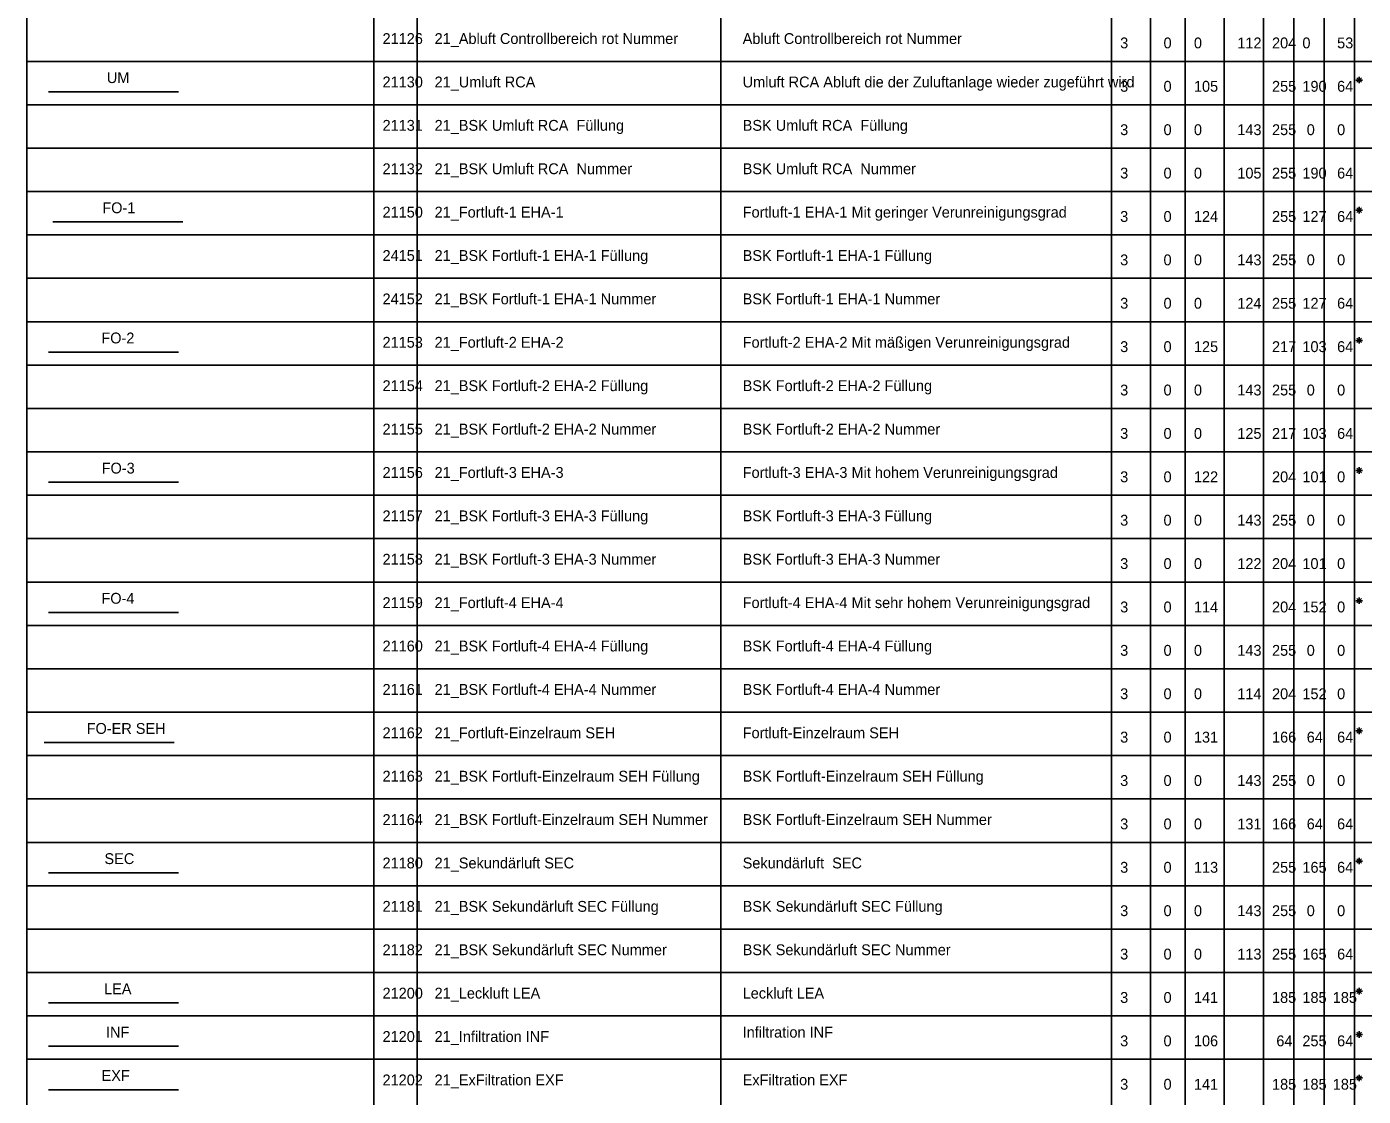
# Model space of a CAD drawing. Extents: x -26 to 55, y -9 to 161.
# Drawn here: x 0 to 30.8, y 52.15 to 76.8 of the extents above; entities that cross this region are included whole.
import ezdxf

# ---------------------------------------------------------------- set-up
doc = ezdxf.new("R2010")
doc.units = 0
for name, color, linetype in [('21_ExFiltration EXF', 7, 'Continuous'), ('21_Fortluft-1 EHA-1', 7, 'Continuous'), ('21_Fortluft-2 EHA-2', 7, 'Continuous'), ('21_Fortluft-3 EHA-3', 7, 'Continuous'), ('21_Fortluft-4 EHA-4', 7, 'Continuous'), ('21_Fortluft-Einezelraum SEH', 7, 'Continuous'), ('21_Infiltration INF', 7, 'Continuous'), ('21_Leckluft LEA', 7, 'Continuous'), ('21_Sekundärluft SEC', 7, 'Continuous'), ('21_Umluft RCA', 7, 'Continuous'), ('Default', 7, 'Continuous')]:
    doc.layers.add(name, color=color, linetype=linetype)

msp = doc.modelspace()

# ---------------------------------------------------------------- linework, layer by layer
at = {"layer": '21_ExFiltration EXF'}
msp.add_line((0.5, 52.3), (3.5, 52.3), dxfattribs=at)
at = {"layer": '21_Fortluft-1 EHA-1'}
msp.add_line((0.6, 72.3), (3.6, 72.3), dxfattribs=at)
at = {"layer": '21_Fortluft-2 EHA-2'}
msp.add_line((0.5, 69.3), (3.5, 69.3), dxfattribs=at)
at = {"layer": '21_Fortluft-3 EHA-3'}
msp.add_line((0.5, 66.3), (3.5, 66.3), dxfattribs=at)
at = {"layer": '21_Fortluft-4 EHA-4'}
msp.add_line((0.5, 63.3), (3.5, 63.3), dxfattribs=at)
at = {"layer": '21_Fortluft-Einezelraum SEH'}
msp.add_line((0.4, 60.3), (3.4, 60.3), dxfattribs=at)
at = {"layer": '21_Infiltration INF'}
msp.add_line((0.5, 53.3), (3.5, 53.3), dxfattribs=at)
at = {"layer": '21_Leckluft LEA'}
msp.add_line((0.5, 54.3), (3.5, 54.3), dxfattribs=at)
at = {"layer": '21_Sekundärluft SEC'}
msp.add_line((0.5, 57.3), (3.5, 57.3), dxfattribs=at)
at = {"layer": '21_Umluft RCA'}
msp.add_line((0.5, 75.3), (3.5, 75.3), dxfattribs=at)
at = {"layer": 'Default'}
for p, q in [((0, 147), (0, 0)), ((8, 147), (8, 0)), ((9, 147), (9, 0)), ((16, 147), (16, 0)), ((25, 147), (25, 0)), ((25.9, 146.3), (25.9, 28)), ((26.7, 146.3), (26.7, 28)), ((27.6, 146.3), (27.6, 28)), ((28.5, 146.3), (28.5, 28)), ((30.6, 146.3), (30.6, 28)), ((29.2, 145.5), (29.2, 28)), ((29.9, 145.5), (29.9, 28)), ((0, 76), (30.383, 76)), ((0, 76), (33.6, 76)), ((30.634, 75.57), (30.786, 75.57)), ((30.657, 75.623), (30.763, 75.517)), ((30.763, 75.623), (30.657, 75.517)), ((30.71, 75.646), (30.71, 75.494)), ((0, 75), (33.6, 75)), ((0, 74), (33.6, 74)), ((0, 73), (33.6, 73)), ((30.634, 72.57), (30.786, 72.57)), ((30.657, 72.623), (30.763, 72.517)), ((30.763, 72.623), (30.657, 72.517)), ((30.71, 72.646), (30.71, 72.494)), ((0, 72), (33.6, 72)), ((0, 71), (33.6, 71)), ((0, 70), (33.6, 70)), ((30.657, 69.623), (30.763, 69.517)), ((30.763, 69.623), (30.657, 69.517)), ((30.71, 69.646), (30.71, 69.494)), ((30.634, 69.57), (30.786, 69.57)), ((0, 69), (33.6, 69)), ((0, 68), (33.6, 68)), ((0, 67), (33.6, 67)), ((30.634, 66.57), (30.786, 66.57)), ((30.657, 66.623), (30.763, 66.517)), ((30.763, 66.623), (30.657, 66.517)), ((30.71, 66.646), (30.71, 66.494)), ((0, 66), (33.6, 66)), ((0, 65), (33.6, 65)), ((0, 64), (33.6, 64)), ((30.634, 63.57), (30.786, 63.57)), ((30.657, 63.623), (30.763, 63.517)), ((30.763, 63.623), (30.657, 63.517)), ((30.71, 63.646), (30.71, 63.494)), ((0, 63), (33.6, 63)), ((0, 62), (33.6, 62)), ((0, 61), (33.6, 61)), ((30.634, 60.57), (30.786, 60.57)), ((30.657, 60.623), (30.763, 60.517)), ((30.763, 60.623), (30.657, 60.517)), ((30.71, 60.646), (30.71, 60.494)), ((0, 60), (33.6, 60)), ((0, 59), (33.6, 59)), ((0, 58), (33.6, 58)), ((30.657, 57.623), (30.763, 57.517)), ((30.763, 57.623), (30.657, 57.517)), ((30.71, 57.646), (30.71, 57.494)), ((30.634, 57.57), (30.786, 57.57)), ((0, 57), (33.6, 57)), ((0, 56), (33.6, 56)), ((0, 55), (33.6, 55)), ((30.634, 54.57), (30.786, 54.57)), ((30.657, 54.623), (30.763, 54.517)), ((30.763, 54.623), (30.657, 54.517)), ((30.71, 54.646), (30.71, 54.494)), ((0, 54), (33.6, 54)), ((30.657, 53.623), (30.763, 53.517)), ((30.763, 53.623), (30.657, 53.517)), ((30.71, 53.646), (30.71, 53.494)), ((30.634, 53.57), (30.786, 53.57)), ((0, 53), (33.6, 53)), ((30.634, 52.57), (30.786, 52.57)), ((30.657, 52.623), (30.763, 52.517)), ((30.763, 52.623), (30.657, 52.517)), ((30.71, 52.646), (30.71, 52.494))]:
    msp.add_line(p, q, dxfattribs=at)

# ---------------------------------------------------------------- texts
at = {"layer": '21_ExFiltration EXF'}
msp.add_text('EXF ', height=0.25, dxfattribs=at).set_placement((1.725, 52.5))
at = {"layer": '21_Fortluft-1 EHA-1'}
msp.add_text('FO-1', height=0.25, dxfattribs=at).set_placement((1.742, 72.5))
at = {"layer": '21_Fortluft-2 EHA-2'}
msp.add_text('FO-2', height=0.25, dxfattribs=at).set_placement((1.72, 69.5))
at = {"layer": '21_Fortluft-3 EHA-3'}
msp.add_text('FO-3', height=0.25, dxfattribs=at).set_placement((1.727, 66.5))
at = {"layer": '21_Fortluft-4 EHA-4'}
msp.add_text('FO-4', height=0.25, dxfattribs=at).set_placement((1.722, 63.5))
at = {"layer": '21_Fortluft-Einezelraum SEH'}
msp.add_text('FO-ER SEH', height=0.25, dxfattribs=at).set_placement((1.381, 60.5))
at = {"layer": '21_Infiltration INF'}
msp.add_text('INF', height=0.25, dxfattribs=at).set_placement((1.827, 53.5))
at = {"layer": '21_Leckluft LEA'}
msp.add_text('LEA', height=0.25, dxfattribs=at).set_placement((1.782, 54.5))
at = {"layer": '21_Sekundärluft SEC'}
msp.add_text('SEC', height=0.25, dxfattribs=at).set_placement((1.792, 57.5))
at = {"layer": '21_Umluft RCA'}
msp.add_text('UM', height=0.25, dxfattribs=at).set_placement((1.846, 75.5))
at = {"layer": 'Default'}
for s, p in [('21126', (8.2, 76.4)), ('21_Abluft Controllbereich rot Nummer', (9.4, 76.4)), ('Abluft Controllbereich rot Nummer', (16.5, 76.4)), ('3', (25.2, 76.3)), ('0', (26.2, 76.3)), ('0', (26.9, 76.3)), ('112', (27.9, 76.3)), ('204', (28.7, 76.3)), ('0', (29.4, 76.3)), ('53', (30.2, 76.3)), ('21130', (8.2, 75.4)), ('21_Umluft RCA ', (9.4, 75.4)), ('Umluft RCA Abluft die der Zuluftanlage wieder zugeführt wird', (16.5, 75.4)), ('3', (25.2, 75.3)), ('0', (26.2, 75.3)), ('105', (26.9, 75.3)), ('255', (28.7, 75.3)), ('190', (29.4, 75.3)), ('64', (30.2, 75.3)), ('21131', (8.2, 74.4)), ('21_BSK Umluft RCA  Füllung', (9.4, 74.4)), ('BSK Umluft RCA  Füllung', (16.5, 74.4)), ('3', (25.2, 74.3)), ('0', (26.2, 74.3)), ('0', (26.9, 74.3)), ('143', (27.9, 74.3)), ('255', (28.7, 74.3)), ('0', (29.5, 74.3)), ('0', (30.2, 74.3)), ('21132', (8.2, 73.4)), ('21_BSK Umluft RCA  Nummer', (9.4, 73.4)), ('BSK Umluft RCA  Nummer', (16.5, 73.4)), ('3', (25.2, 73.3)), ('0', (26.2, 73.3)), ('0', (26.9, 73.3)), ('105', (27.9, 73.3)), ('255', (28.7, 73.3)), ('190', (29.4, 73.3)), ('64', (30.2, 73.3)), ('21150', (8.2, 72.4)), ('21_Fortluft-1 EHA-1', (9.4, 72.4)), ('Fortluft-1 EHA-1 Mit geringer Verunreinigungsgrad', (16.5, 72.4)), ('3', (25.2, 72.3)), ('0', (26.2, 72.3)), ('124', (26.9, 72.3)), ('255', (28.7, 72.3)), ('127', (29.4, 72.3)), ('64', (30.2, 72.3)), ('24151', (8.2, 71.4)), ('21_BSK Fortluft-1 EHA-1 Füllung', (9.4, 71.4)), ('BSK Fortluft-1 EHA-1 Füllung', (16.5, 71.4)), ('3', (25.2, 71.3)), ('0', (26.2, 71.3)), ('0', (26.9, 71.3)), ('143', (27.9, 71.3)), ('255', (28.7, 71.3)), ('0', (29.5, 71.3)), ('0', (30.2, 71.3)), ('24152', (8.2, 70.4)), ('21_BSK Fortluft-1 EHA-1 Nummer', (9.4, 70.4)), ('BSK Fortluft-1 EHA-1 Nummer', (16.5, 70.4)), ('3', (25.2, 70.3)), ('0', (26.2, 70.3)), ('0', (26.9, 70.3)), ('124', (27.9, 70.3)), ('255', (28.7, 70.3)), ('127', (29.4, 70.3)), ('64', (30.2, 70.3)), ('21153', (8.2, 69.4)), ('21_Fortluft-2 EHA-2', (9.4, 69.4)), ('Fortluft-2 EHA-2 Mit mäßigen Verunreinigungsgrad', (16.5, 69.4)), ('3', (25.2, 69.3)), ('0', (26.2, 69.3)), ('125', (26.9, 69.3)), ('217', (28.7, 69.3)), ('103', (29.4, 69.3)), ('64', (30.2, 69.3)), ('21154', (8.2, 68.4)), ('21_BSK Fortluft-2 EHA-2 Füllung', (9.4, 68.4)), ('BSK Fortluft-2 EHA-2 Füllung', (16.5, 68.4)), ('3', (25.2, 68.3)), ('0', (26.2, 68.3)), ('0', (26.9, 68.3)), ('143', (27.9, 68.3)), ('255', (28.7, 68.3)), ('0', (29.5, 68.3)), ('0', (30.2, 68.3)), ('21155', (8.2, 67.4)), ('21_BSK Fortluft-2 EHA-2 Nummer', (9.4, 67.4)), ('BSK Fortluft-2 EHA-2 Nummer', (16.5, 67.4)), ('3', (25.2, 67.3)), ('0', (26.2, 67.3)), ('0', (26.9, 67.3)), ('125', (27.9, 67.3)), ('217', (28.7, 67.3)), ('103', (29.4, 67.3)), ('64', (30.2, 67.3)), ('21156', (8.2, 66.4)), ('21_Fortluft-3 EHA-3', (9.4, 66.4)), ('Fortluft-3 EHA-3 Mit hohem Verunreinigungsgrad', (16.5, 66.4)), ('3', (25.2, 66.3)), ('0', (26.2, 66.3)), ('122', (26.9, 66.3)), ('204', (28.7, 66.3)), ('101', (29.4, 66.3)), ('0', (30.2, 66.3)), ('21157', (8.2, 65.4)), ('21_BSK Fortluft-3 EHA-3 Füllung', (9.4, 65.4)), ('BSK Fortluft-3 EHA-3 Füllung', (16.5, 65.4)), ('3', (25.2, 65.3)), ('0', (26.2, 65.3)), ('0', (26.9, 65.3)), ('143', (27.9, 65.3)), ('255', (28.7, 65.3)), ('0', (29.5, 65.3)), ('0', (30.2, 65.3)), ('21158', (8.2, 64.4)), ('21_BSK Fortluft-3 EHA-3 Nummer', (9.4, 64.4)), ('BSK Fortluft-3 EHA-3 Nummer', (16.5, 64.4)), ('3', (25.2, 64.3)), ('0', (26.2, 64.3)), ('0', (26.9, 64.3)), ('122', (27.9, 64.3)), ('204', (28.7, 64.3)), ('101', (29.4, 64.3)), ('0', (30.2, 64.3)), ('21159', (8.2, 63.4)), ('21_Fortluft-4 EHA-4', (9.4, 63.4)), ('Fortluft-4 EHA-4 Mit sehr hohem Verunreinigungsgrad', (16.5, 63.4)), ('3', (25.2, 63.3)), ('0', (26.2, 63.3)), ('114', (26.9, 63.3)), ('204', (28.7, 63.3)), ('152', (29.4, 63.3)), ('0', (30.2, 63.3)), ('21160', (8.2, 62.4)), ('21_BSK Fortluft-4 EHA-4 Füllung', (9.4, 62.4)), ('BSK Fortluft-4 EHA-4 Füllung', (16.5, 62.4)), ('3', (25.2, 62.3)), ('0', (26.2, 62.3)), ('0', (26.9, 62.3)), ('143', (27.9, 62.3)), ('255', (28.7, 62.3)), ('0', (29.5, 62.3)), ('0', (30.2, 62.3)), ('21161', (8.2, 61.4)), ('21_BSK Fortluft-4 EHA-4 Nummer', (9.4, 61.4)), ('BSK Fortluft-4 EHA-4 Nummer', (16.5, 61.4)), ('3', (25.2, 61.3)), ('0', (26.2, 61.3)), ('0', (26.9, 61.3)), ('114', (27.9, 61.3)), ('204', (28.7, 61.3)), ('204', (28.7, 61.3)), ('152', (29.4, 61.3)), ('152', (29.4, 61.3)), ('0', (30.2, 61.3)), ('0', (30.2, 61.3)), ('21162', (8.2, 60.4)), ('21_Fortluft-Einzelraum SEH', (9.4, 60.4)), ('Fortluft-Einzelraum SEH', (16.5, 60.4)), ('3', (25.2, 60.3)), ('0', (26.2, 60.3)), ('131', (26.9, 60.3)), ('166', (28.7, 60.3)), ('64', (29.5, 60.3)), ('64', (30.2, 60.3)), ('21163', (8.2, 59.4)), ('21_BSK Fortluft-Einzelraum SEH Füllung', (9.4, 59.4)), ('BSK Fortluft-Einzelraum SEH Füllung', (16.5, 59.4)), ('3', (25.2, 59.3)), ('0', (26.2, 59.3)), ('0', (26.9, 59.3)), ('143', (27.9, 59.3)), ('255', (28.7, 59.3)), ('0', (29.5, 59.3)), ('0', (30.2, 59.3)), ('21164', (8.2, 58.4)), ('21_BSK Fortluft-Einzelraum SEH Nummer', (9.4, 58.4)), ('BSK Fortluft-Einzelraum SEH Nummer', (16.5, 58.4)), ('3', (25.2, 58.3)), ('0', (26.2, 58.3)), ('0', (26.9, 58.3)), ('131', (27.9, 58.3)), ('166', (28.7, 58.3)), ('64', (29.5, 58.3)), ('64', (30.2, 58.3)), ('21180', (8.2, 57.4)), ('21_Sekundärluft SEC ', (9.4, 57.4)), ('Sekundärluft  SEC ', (16.5, 57.4)), ('3', (25.2, 57.3)), ('0', (26.2, 57.3)), ('113', (26.9, 57.3)), ('255', (28.7, 57.3)), ('165', (29.4, 57.3)), ('64', (30.2, 57.3)), ('21181', (8.2, 56.4)), ('21_BSK Sekundärluft SEC Füllung', (9.4, 56.4)), ('BSK Sekundärluft SEC Füllung', (16.5, 56.4)), ('3', (25.2, 56.3)), ('0', (26.2, 56.3)), ('0', (26.9, 56.3)), ('143', (27.9, 56.3)), ('255', (28.7, 56.3)), ('0', (29.5, 56.3)), ('0', (30.2, 56.3)), ('21182', (8.2, 55.4)), ('21_BSK Sekundärluft SEC Nummer', (9.4, 55.4)), ('BSK Sekundärluft SEC Nummer', (16.5, 55.4)), ('3', (25.2, 55.3)), ('0', (26.2, 55.3)), ('0', (26.9, 55.3)), ('113', (27.9, 55.3)), ('255', (28.7, 55.3)), ('165', (29.4, 55.3)), ('64', (30.2, 55.3)), ('21200', (8.2, 54.4)), ('21_Leckluft LEA ', (9.4, 54.4)), ('Leckluft LEA ', (16.5, 54.4)), ('3', (25.2, 54.3)), ('0', (26.2, 54.3)), ('141', (26.9, 54.3)), ('185', (28.7, 54.3)), ('185', (29.4, 54.3)), ('185', (30.1, 54.3)), ('21201', (8.2, 53.4)), ('21_Infiltration INF ', (9.4, 53.4)), ('Infiltration INF ', (16.5, 53.5)), ('3', (25.2, 53.3)), ('0', (26.2, 53.3)), ('106', (26.9, 53.3)), ('64', (28.8, 53.3)), ('255', (29.4, 53.3)), ('64', (30.2, 53.3)), ('21202', (8.2, 52.4)), ('21_ExFiltration EXF ', (9.4, 52.4)), ('ExFiltration EXF ', (16.5, 52.4)), ('3', (25.2, 52.3)), ('0', (26.2, 52.3)), ('141', (26.9, 52.3)), ('185', (28.7, 52.3)), ('185', (29.4, 52.3)), ('185', (30.1, 52.3))]:
    msp.add_text(s, height=0.25, dxfattribs=at).set_placement(p)

doc.saveas('drawing.dxf')
